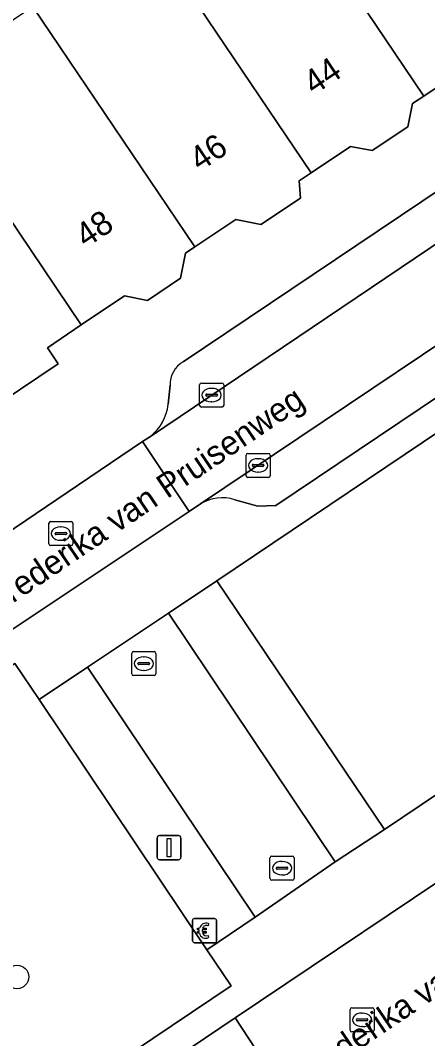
# Model space of a CAD drawing. Extents: x 159960 to 160866, y 382700 to 383354.
# Drawn here: x 160459.7 to 160476.6, y 382881 to 382923.27 of the extents above; entities that cross this region are included whole.
import ezdxf

# ---------------------------------------------------------------- set-up
doc = ezdxf.new("R2010")
doc.units = 0
for name, color, linetype in [('IMGEO_Betaalautomaat', 7, 'Continuous'), ('IMGEO_Boom', 7, 'Continuous'), ('IMGEO_Groenvoorziening', 7, 'Continuous'), ('IMGEO_Kolk', 7, 'Continuous'), ('IMGEO_Lichtmast', 7, 'Continuous'), ('IMGEO_Openbare_ruimte_label', 7, 'Continuous'), ('IMGEO_Pand', 7, 'Continuous'), ('IMGEO_Pand_nummerreeks', 7, 'Continuous'), ('IMGEO_Parkeervlak_open', 7, 'Continuous'), ('IMGEO_Rijbaan_lokaal_gesloten', 7, 'Continuous'), ('IMGEO_Rijbaan_lokaal_open', 7, 'Continuous'), ('IMGEO_Rioolput', 7, 'Continuous'), ('IMGEO_Voetpad_open', 7, 'Continuous')]:
    doc.layers.add(name, color=color, linetype=linetype)

msp = doc.modelspace()

# ---------------------------------------------------------------- linework, layer by layer
at = {"layer": 'IMGEO_Betaalautomaat'}
for p, q in [((160466.846, 382885.055), (160466.846, 382885.896)), ((160466.846, 382885.896), (160466.846, 382885.055)), ((160466.921, 382885.979), (160467.762, 382885.979)), ((160467.762, 382885.979), (160466.921, 382885.979)), ((160467.508, 382885.784), (160467.491, 382885.684)), ((160467.845, 382885.905), (160467.845, 382885.064)), ((160467.845, 382885.064), (160467.845, 382885.905)), ((160467.129, 382885.443), (160467.129, 382885.511)), ((160467.25, 382885.511), (160467.25, 382885.443)), ((160467.495, 382885.278), (160467.517, 382885.191)), ((160467.771, 382884.98), (160466.93, 382884.98)), ((160466.93, 382884.98), (160467.771, 382884.98))]:
    msp.add_line(p, q, dxfattribs=at)
for points in [[(160467.129, 382885.511), (160467.06, 382885.511), (160467.06, 382885.58), (160467.139, 382885.58)], [(160467.261, 382885.58), (160467.408, 382885.58), (160467.408, 382885.511), (160467.25, 382885.511)], [(160467.134, 382885.374), (160467.06, 382885.374), (160467.06, 382885.443), (160467.129, 382885.443)], [(160467.25, 382885.443), (160467.408, 382885.443), (160467.408, 382885.374), (160467.264, 382885.374)]]:
    msp.add_lwpolyline(points, dxfattribs=at)
for centre, radius, start, end in [((160466.924, 382885.902), 0.0779, 92.4484, 184.2845), ((160466.924, 382885.902), 0.0779, 92.4484, 184.2845), ((160467.422, 382885.504), 0.293, 73.014, 165.0139), ((160467.428, 382885.517), 0.179, 69.3236, 159.5683), ((160467.768, 382885.902), 0.0779, 2.4484, 94.2845), ((160467.768, 382885.902), 0.0779, 2.4484, 94.2845), ((160467.395, 382885.429), 0.267, 191.8096, 297.0389), ((160467.428, 382885.444), 0.179, 202.7625, 291.8693), ((160466.924, 382885.058), 0.0779, 182.4484, 274.2845), ((160466.924, 382885.058), 0.0779, 182.4484, 274.2845), ((160467.768, 382885.058), 0.0779, 272.4484, 4.2845), ((160467.768, 382885.058), 0.0779, 272.4484, 4.2845)]:
    msp.add_arc(centre, radius, start, end, dxfattribs=at)
at = {"layer": 'IMGEO_Boom'}
msp.add_circle((160459.562, 382883.56), 0.489, dxfattribs=at)
at = {"layer": 'IMGEO_Groenvoorziening'}
for points in [[(160474.811, 382889.677), (160500, 382906.637), (160502.13, 382908.071), (160500, 382911.244), (160495.193, 382918.403), (160467.857, 382900.011)], [(160443.538, 382867.502), (160445.107, 382868.54), (160445.597, 382867.827), (160468.445, 382883.188), (160467.44, 382884.688), (160460.477, 382895.074), (160459.475, 382896.568), (160435.03, 382880.147)]]:
    msp.add_lwpolyline(points, close=True, dxfattribs=at)
at = {"layer": 'IMGEO_Kolk'}
for p, q in [((160467.14, 382907.291), (160467.14, 382908.143)), ((160467.215, 382908.217), (160468.067, 382908.217)), ((160467.628, 382907.997), (160467.653, 382907.997)), ((160468.141, 382908.143), (160468.141, 382907.291)), ((160467.399, 382907.711), (160467.399, 382907.723)), ((160467.837, 382907.674), (160467.439, 382907.674)), ((160467.442, 382907.76), (160467.84, 382907.76)), ((160467.883, 382907.723), (160467.883, 382907.711)), ((160468.067, 382907.217), (160467.215, 382907.217)), ((160467.651, 382907.437), (160467.626, 382907.437)), ((160469.071, 382904.37), (160469.071, 382905.222)), ((160469.146, 382905.296), (160469.998, 382905.296)), ((160469.559, 382905.076), (160469.584, 382905.076)), ((160470.072, 382905.222), (160470.072, 382904.37)), ((160469.33, 382904.79), (160469.33, 382904.802)), ((160469.768, 382904.753), (160469.37, 382904.753)), ((160469.373, 382904.839), (160469.771, 382904.839)), ((160469.814, 382904.802), (160469.814, 382904.79)), ((160469.998, 382904.296), (160469.146, 382904.296)), ((160469.582, 382904.516), (160469.557, 382904.516)), ((160464.325, 382896.142), (160464.325, 382896.994)), ((160464.4, 382897.068), (160465.252, 382897.068)), ((160465.326, 382896.994), (160465.326, 382896.142)), ((160464.584, 382896.562), (160464.584, 382896.574)), ((160464.627, 382896.611), (160465.025, 382896.611)), ((160464.813, 382896.848), (160464.838, 382896.848)), ((160465.068, 382896.574), (160465.068, 382896.562)), ((160465.022, 382896.525), (160464.624, 382896.525)), ((160464.836, 382896.288), (160464.811, 382896.288)), ((160465.252, 382896.068), (160464.4, 382896.068)), ((160470.138, 382888.575), (160470.99, 382888.575)), ((160470.063, 382887.649), (160470.063, 382888.501)), ((160470.365, 382888.118), (160470.763, 382888.118)), ((160470.551, 382888.355), (160470.576, 382888.355)), ((160471.064, 382888.501), (160471.064, 382887.649)), ((160470.322, 382888.069), (160470.322, 382888.081)), ((160470.76, 382888.032), (160470.362, 382888.032)), ((160470.574, 382887.795), (160470.549, 382887.795)), ((160470.806, 382888.081), (160470.806, 382888.069)), ((160470.99, 382887.575), (160470.138, 382887.575))]:
    msp.add_line(p, q, dxfattribs=at)
for points in [[(160467.14, 382907.291), (160467.14, 382908.143)], [(160467.215, 382908.217), (160468.067, 382908.217)], [(160468.141, 382908.143), (160468.141, 382907.291)], [(160468.067, 382907.217), (160467.215, 382907.217)], [(160469.071, 382904.37), (160469.071, 382905.222)], [(160469.146, 382905.296), (160469.998, 382905.296)], [(160470.072, 382905.222), (160470.072, 382904.37)], [(160469.998, 382904.296), (160469.146, 382904.296)], [(160464.325, 382896.142), (160464.325, 382896.994)], [(160464.4, 382897.068), (160465.252, 382897.068)], [(160465.326, 382896.994), (160465.326, 382896.142)], [(160465.252, 382896.068), (160464.4, 382896.068)], [(160470.138, 382888.575), (160470.99, 382888.575)], [(160470.063, 382887.649), (160470.063, 382888.501)], [(160471.064, 382888.501), (160471.064, 382887.649)], [(160470.99, 382887.575), (160470.138, 382887.575)]]:
    msp.add_lwpolyline(points, dxfattribs=at)
for centre, radius, start, end in [((160467.217, 382908.141), 0.0765, 91.552, 178.448), ((160467.217, 382908.141), 0.0765, 91.552, 178.448), ((160468.065, 382908.141), 0.0765, 1.552, 88.448), ((160468.065, 382908.141), 0.0765, 1.552, 88.448), ((160467.439, 382907.72), 0.0403, 85.8775, 175.7526), ((160467.436, 382907.71), 0.0366, 178.938, 274.7102), ((160467.84, 382907.717), 0.043, 264.8664, 352.4533), ((160467.844, 382907.722), 0.0386, 1.7309, 96.639), ((160467.217, 382907.293), 0.0765, 181.552, 268.448), ((160467.217, 382907.293), 0.0765, 181.552, 268.448), ((160468.065, 382907.293), 0.0765, 271.552, 358.448), ((160468.065, 382907.293), 0.0765, 271.552, 358.448), ((160469.148, 382905.22), 0.0765, 91.552, 178.448), ((160469.148, 382905.22), 0.0765, 91.552, 178.448), ((160469.996, 382905.22), 0.0765, 1.552, 88.448), ((160469.996, 382905.22), 0.0765, 1.552, 88.448), ((160469.37, 382904.799), 0.0403, 85.8775, 175.7526), ((160469.367, 382904.789), 0.0366, 178.938, 274.7102), ((160469.771, 382904.796), 0.043, 264.8664, 352.4533), ((160469.775, 382904.801), 0.0386, 1.7309, 96.639), ((160469.148, 382904.372), 0.0765, 181.552, 268.448), ((160469.148, 382904.372), 0.0765, 181.552, 268.448), ((160469.996, 382904.372), 0.0765, 271.552, 358.448), ((160469.996, 382904.372), 0.0765, 271.552, 358.448), ((160464.402, 382896.992), 0.0765, 91.552, 178.448), ((160464.402, 382896.992), 0.0765, 91.552, 178.448), ((160465.25, 382896.992), 0.0765, 1.552, 88.448), ((160465.25, 382896.992), 0.0765, 1.552, 88.448), ((160464.624, 382896.571), 0.0403, 85.8775, 175.7526), ((160464.621, 382896.561), 0.0366, 178.938, 274.7102), ((160465.025, 382896.568), 0.043, 264.8664, 352.4533), ((160465.029, 382896.573), 0.0386, 1.7309, 96.639), ((160464.402, 382896.144), 0.0765, 181.552, 268.448), ((160464.402, 382896.144), 0.0765, 181.552, 268.448), ((160465.25, 382896.144), 0.0765, 271.552, 358.448), ((160465.25, 382896.144), 0.0765, 271.552, 358.448), ((160470.14, 382888.499), 0.0765, 91.552, 178.448), ((160470.14, 382888.499), 0.0765, 91.552, 178.448), ((160470.988, 382888.499), 0.0765, 1.552, 88.448), ((160470.988, 382888.499), 0.0765, 1.552, 88.448), ((160470.362, 382888.078), 0.0403, 85.8775, 175.7526), ((160470.767, 382888.08), 0.0386, 1.7309, 96.639), ((160470.359, 382888.068), 0.0366, 178.938, 274.7102), ((160470.763, 382888.075), 0.043, 264.8664, 352.4533), ((160470.14, 382887.651), 0.0765, 181.552, 268.448), ((160470.14, 382887.651), 0.0765, 181.552, 268.448), ((160470.988, 382887.651), 0.0765, 271.552, 358.448), ((160470.988, 382887.651), 0.0765, 271.552, 358.448)]:
    msp.add_arc(centre, radius, start, end, dxfattribs=at)
for centre, major_axis, ratio, start_param, end_param in [((160467.627, 382907.717), (-0.387, 0.002), 0.722429, 4.712389, 7.853982), ((160467.652, 382907.717), (-0.39, 0.002), 0.717154, 1.570796, 4.712389), ((160469.558, 382904.796), (-0.387, 0.002), 0.722429, 4.712389, 7.853982), ((160469.583, 382904.796), (-0.39, 0.002), 0.717154, 1.570796, 4.712389), ((160464.812, 382896.568), (-0.387, 0.002), 0.722429, 4.712389, 7.853982), ((160464.837, 382896.568), (-0.39, 0.002), 0.717154, 1.570796, 4.712389), ((160470.55, 382888.075), (-0.387, 0.002), 0.722429, 4.712389, 7.853982), ((160470.575, 382888.075), (-0.39, 0.002), 0.717154, 1.570796, 4.712389)]:
    msp.add_ellipse(centre, major_axis=major_axis, ratio=ratio, start_param=start_param, end_param=end_param, dxfattribs=at)
at = {"layer": 'IMGEO_Lichtmast'}
for p, q in [((160465.478, 382889.427), (160466.268, 382889.427)), ((160466.268, 382889.427), (160465.478, 382889.427)), ((160465.378, 382888.527), (160465.378, 382889.327)), ((160465.378, 382889.327), (160465.378, 382888.527)), ((160466.368, 382889.327), (160466.368, 382888.527)), ((160466.368, 382888.527), (160466.368, 382889.327)), ((160466.268, 382888.427), (160465.478, 382888.427)), ((160465.478, 382888.427), (160466.268, 382888.427))]:
    msp.add_line(p, q, dxfattribs=at)
msp.add_lwpolyline([(160465.798, 382889.302), (160465.948, 382889.302), (160465.948, 382888.552), (160465.798, 382888.552), (160465.798, 382889.302)], dxfattribs=at)
for centre, start, end in [((160465.478, 382889.327), 90, 180), ((160465.478, 382889.327), 90, 180), ((160466.268, 382889.327), 0, 90), ((160466.268, 382889.327), 360, 90), ((160465.478, 382888.527), 180, 270), ((160465.478, 382888.527), 180, 270), ((160466.268, 382888.527), 270, 0), ((160466.268, 382888.527), 270, 0)]:
    msp.add_arc(centre, 0.1, start, end, dxfattribs=at)
at = {"layer": 'IMGEO_Pand'}
for points in [[(160474.384, 382933.325), (160469.677, 382930.171), (160476.442, 382920.132), (160478.032, 382921.197), (160478.964, 382921.013), (160480.592, 382922.103), (160480.535, 382922.957), (160481.11, 382923.342)], [(160476.442, 382920.132), (160469.677, 382930.171), (160464.977, 382927.022), (160471.767, 382916.945), (160473.407, 382918.043), (160474.31, 382917.865), (160475.784, 382918.853), (160475.975, 382919.819)], [(160460.225, 382923.839), (160466.946, 382913.865), (160468.645, 382915.003), (160469.681, 382914.798), (160471.324, 382915.899), (160471.276, 382916.616), (160471.767, 382916.945), (160464.977, 382927.022)], [(160460.225, 382923.839), (160455.475, 382920.656), (160462.233, 382910.627), (160464.031, 382911.832), (160464.973, 382911.645), (160466.349, 382912.567), (160466.554, 382913.602), (160466.946, 382913.865)], [(160462.233, 382910.627), (160455.475, 382920.656), (160450.884, 382917.58), (160458.095, 382906.88), (160461.277, 382909.012), (160460.826, 382909.684)]]:
    msp.add_lwpolyline(points, close=True, dxfattribs=at)
at = {"layer": 'IMGEO_Parkeervlak_open'}
for points in [[(160465.099, 382906.001), (160495.672, 382926.63)], [(160492.593, 382926.669), (160466.455, 382909.096)], [(160496.919, 382923.173), (160493.768, 382921.059), (160467.177, 382903.196)], [(160468.603, 382903.37), (160469.558, 382903.103), (160470.311, 382903.129), (160492.538, 382918.084)], [(160465.922, 382908.125), (160465.835, 382907.334)]]:
    msp.add_lwpolyline(points, dxfattribs=at)
for centre, radius, start, end in [((160467.004, 382908.163), 1.083, 120.4667, 182.0069), ((160463.937, 382907.512), 1.906, 307.5519, 354.6386), ((160468.075, 382901.763), 1.691, 71.8215, 122.0921)]:
    msp.add_arc(centre, radius, start, end, dxfattribs=at)
at = {"layer": 'IMGEO_Rijbaan_lokaal_gesloten'}
msp.add_lwpolyline([(160428.137, 382852.75), (160469.463, 382880.579), (160468.612, 382881.856), (160427.286, 382854.001)], close=True, dxfattribs=at)
at = {"layer": 'IMGEO_Rijbaan_lokaal_open'}
for points in [[(160493.768, 382921.059), (160496.919, 382923.173), (160498.009, 382923.904), (160496.024, 382926.864), (160495.846, 382926.747), (160495.672, 382926.63), (160465.099, 382906.001), (160464.776, 382905.783), (160466.706, 382902.882), (160467.177, 382903.196)], [(160458.264, 382897.258), (160466.706, 382902.882), (160464.776, 382905.783), (160456.356, 382900.103)], [(160469.445, 382886.045), (160472.772, 382888.331), (160465.846, 382898.668), (160462.489, 382896.421)], [(160477.885, 382886.287), (160477.075, 382887.533), (160468.612, 382881.856), (160469.463, 382880.579), (160471.37, 382877.716), (160472.191, 382876.484), (160480.656, 382882.178), (160479.808, 382883.436)]]:
    msp.add_lwpolyline(points, close=True, dxfattribs=at)
at = {"layer": 'IMGEO_Rioolput'}
for p, q in [((160460.883, 382901.542), (160460.883, 382902.394)), ((160460.958, 382902.468), (160461.81, 382902.468)), ((160461.371, 382902.248), (160461.396, 382902.248)), ((160461.884, 382902.394), (160461.884, 382901.542)), ((160461.142, 382901.962), (160461.142, 382901.974)), ((160461.58, 382901.925), (160461.182, 382901.925)), ((160461.185, 382902.011), (160461.583, 382902.011)), ((160461.394, 382901.688), (160461.369, 382901.688)), ((160461.626, 382901.974), (160461.626, 382901.962)), ((160461.81, 382901.468), (160460.958, 382901.468)), ((160473.386, 382881.352), (160473.386, 382882.204)), ((160473.461, 382882.278), (160474.313, 382882.278)), ((160474.387, 382882.204), (160474.387, 382881.352)), ((160473.645, 382881.772), (160473.645, 382881.784)), ((160473.688, 382881.821), (160474.086, 382881.821)), ((160473.874, 382882.058), (160473.899, 382882.058)), ((160474.129, 382881.784), (160474.129, 382881.772)), ((160474.083, 382881.735), (160473.685, 382881.735)), ((160473.897, 382881.498), (160473.872, 382881.498)), ((160474.313, 382881.278), (160473.461, 382881.278))]:
    msp.add_line(p, q, dxfattribs=at)
for points in [[(160460.883, 382901.542), (160460.883, 382902.394)], [(160460.958, 382902.468), (160461.81, 382902.468)], [(160461.884, 382902.394), (160461.884, 382901.542)], [(160461.81, 382901.468), (160460.958, 382901.468)], [(160473.386, 382881.352), (160473.386, 382882.204)], [(160473.461, 382882.278), (160474.313, 382882.278)], [(160474.387, 382882.204), (160474.387, 382881.352)], [(160474.313, 382881.278), (160473.461, 382881.278)]]:
    msp.add_lwpolyline(points, dxfattribs=at)
for centre, radius, start, end in [((160460.96, 382902.392), 0.0765, 91.552, 178.448), ((160460.96, 382902.392), 0.0765, 91.552, 178.448), ((160461.808, 382902.392), 0.0765, 1.552, 88.448), ((160461.808, 382902.392), 0.0765, 1.552, 88.448), ((160461.182, 382901.971), 0.0403, 85.8775, 175.7526), ((160461.179, 382901.961), 0.0366, 178.938, 274.7102), ((160461.583, 382901.968), 0.043, 264.8664, 352.4533), ((160461.587, 382901.973), 0.0386, 1.7309, 96.639), ((160460.96, 382901.544), 0.0765, 181.552, 268.448), ((160460.96, 382901.544), 0.0765, 181.552, 268.448), ((160461.808, 382901.544), 0.0765, 271.552, 358.448), ((160461.808, 382901.544), 0.0765, 271.552, 358.448), ((160473.463, 382882.202), 0.0765, 91.552, 178.448), ((160473.463, 382882.202), 0.0765, 91.552, 178.448), ((160474.311, 382882.202), 0.0765, 1.552, 88.448), ((160474.311, 382882.202), 0.0765, 1.552, 88.448), ((160473.685, 382881.781), 0.0403, 85.8775, 175.7526), ((160473.682, 382881.771), 0.0366, 178.938, 274.7102), ((160474.086, 382881.778), 0.043, 264.8664, 352.4533), ((160474.09, 382881.783), 0.0386, 1.7309, 96.639), ((160473.463, 382881.354), 0.0765, 181.552, 268.448), ((160473.463, 382881.354), 0.0765, 181.552, 268.448), ((160474.311, 382881.354), 0.0765, 271.552, 358.448), ((160474.311, 382881.354), 0.0765, 271.552, 358.448)]:
    msp.add_arc(centre, radius, start, end, dxfattribs=at)
for centre, major_axis, ratio, start_param, end_param in [((160461.37, 382901.968), (-0.387, 0.002), 0.722429, 4.712389, 7.853982), ((160461.395, 382901.968), (-0.39, 0.002), 0.717154, 1.570796, 4.712389), ((160473.873, 382881.778), (-0.387, 0.002), 0.722429, 4.712389, 7.853982), ((160473.898, 382881.778), (-0.39, 0.002), 0.717154, 1.570796, 4.712389)]:
    msp.add_ellipse(centre, major_axis=major_axis, ratio=ratio, start_param=start_param, end_param=end_param, dxfattribs=at)
at = {"layer": 'IMGEO_Voetpad_open'}
for points in [[(160410.07, 382861.949), (160415.268, 382865.398), (160416.783, 382866.403), (160416.621, 382866.647), (160416.118, 382867.403), (160433.527, 382879.124), (160435.03, 382880.147), (160459.475, 382896.568), (160460.477, 382895.074), (160462.489, 382896.421), (160465.846, 382898.668), (160467.857, 382900.011), (160495.193, 382918.403), (160496.721, 382919.422), (160500, 382921.626), (160543.226, 382950.68), (160544.698, 382951.695), (160563.415, 382964.323)], [(160466.455, 382909.096), (160492.593, 382926.669)], [(160527.954, 382923.207), (160504.654, 382907.546), (160503.626, 382909.085), (160502.13, 382908.071), (160500, 382906.637), (160474.811, 382889.677), (160472.772, 382888.331), (160469.445, 382886.045), (160467.44, 382884.688), (160468.445, 382883.188), (160445.597, 382867.827), (160445.107, 382868.54), (160443.538, 382867.502), (160442.031, 382866.486), (160440.445, 382865.416), (160440.949, 382864.662), (160425.07, 382853.944), (160424.571, 382854.695), (160423.073, 382853.686), (160421.869, 382852.868), (160419.321, 382851.159)], [(160481.11, 382923.342), (160480.535, 382922.957), (160480.592, 382922.103), (160478.964, 382921.013), (160478.032, 382921.197), (160476.442, 382920.132), (160475.975, 382919.819), (160475.784, 382918.853), (160474.31, 382917.865), (160473.407, 382918.043), (160471.767, 382916.945), (160471.276, 382916.616), (160471.324, 382915.899), (160469.681, 382914.798), (160468.645, 382915.003), (160466.946, 382913.865), (160466.554, 382913.602), (160466.349, 382912.567), (160464.973, 382911.645), (160464.031, 382911.832), (160462.233, 382910.627), (160460.826, 382909.684), (160461.277, 382909.012), (160458.095, 382906.88)], [(160495.983, 382920.426), (160492.538, 382918.084), (160470.311, 382903.129), (160469.558, 382903.103), (160468.603, 382903.37)], [(160465.835, 382907.334), (160465.922, 382908.125)], [(160453.54, 382898.204), (160456.356, 382900.103), (160464.776, 382905.783), (160465.099, 382906.001)], [(160467.177, 382903.196), (160466.706, 382902.882), (160458.264, 382897.258), (160421.52, 382872.518), (160415.611, 382868.38), (160413.308, 382866.834), (160406.587, 382862.392), (160408.916, 382860.279)], [(160420.504, 382849.436), (160422.365, 382850.709), (160424.196, 382851.918), (160424.964, 382852.436), (160427.286, 382854.001), (160468.612, 382881.856), (160477.075, 382887.533), (160480.304, 382889.735)]]:
    msp.add_lwpolyline(points, dxfattribs=at)
for points in [[(160467.857, 382900.011), (160465.846, 382898.668), (160472.772, 382888.331), (160474.811, 382889.677)], [(160462.489, 382896.421), (160460.477, 382895.074), (160467.44, 382884.688), (160469.445, 382886.045)]]:
    msp.add_lwpolyline(points, close=True, dxfattribs=at)
for centre, radius, start, end in [((160467.004, 382908.163), 1.083, 120.4667, 182.0069), ((160463.937, 382907.512), 1.906, 307.5519, 354.6386), ((160468.075, 382901.763), 1.691, 71.8215, 122.0921)]:
    msp.add_arc(centre, radius, start, end, dxfattribs=at)

# ---------------------------------------------------------------- texts
at = {"layer": 'IMGEO_Openbare_ruimte_label'}
for p in [(160458.715, 382898.604), (160471.462, 382878.971)]:
    msp.add_text('Frederika van Pruisenweg', height=1, rotation=34.0716, dxfattribs=at).set_placement(p)
at = {"layer": 'IMGEO_Pand_nummerreeks'}
for s, p in [('44', (160471.883, 382920.15)), ('46', (160467.15, 382916.976)), ('48', (160462.418, 382913.804))]:
    msp.add_text(s, height=1, rotation=33.8397, dxfattribs=at).set_placement(p)

doc.saveas('drawing.dxf')
